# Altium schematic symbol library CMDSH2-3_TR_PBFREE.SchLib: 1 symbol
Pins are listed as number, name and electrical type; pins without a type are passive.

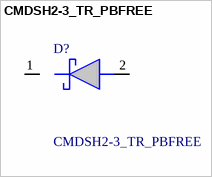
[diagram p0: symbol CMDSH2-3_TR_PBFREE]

## CMDSH2-3_TR_PBFREE
designator D?
DIODE SCHOTTKY 30V 200MA SOD323; Manufacturer_Name: Central Semiconductor; Manufacturer_Part_Number: CMDSH2-3 TR PBFREE; Geometry.Height: 1.1mm
footprint SOD2512X110N
pins: 1 K, 2 A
